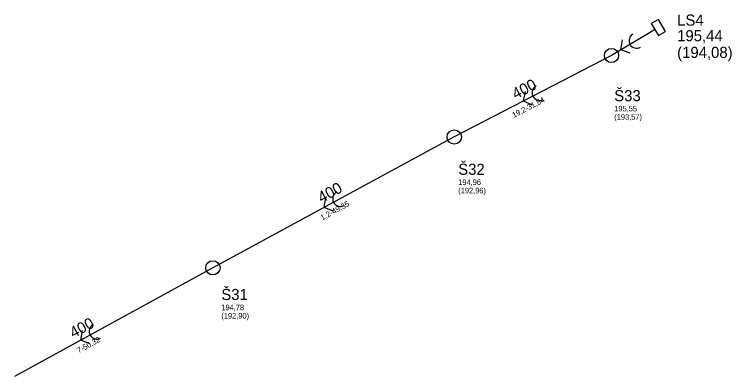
# Model space of a CAD drawing. Extents: x -574467 to -573663, y -1191209 to -1190406.
# Drawn here: x -574467.2 to -574338.3, y -1190987.7 to -1190922.6 of the extents above; entities that cross this region are included whole.
import ezdxf

# ---------------------------------------------------------------- set-up
doc = ezdxf.new("R2010")
doc.units = 0
for name, color, linetype in [('Vrstva 1', 7, 'Continuous'), ('Vrstva 15', 7, 'Continuous'), ('Vrstva 29', 7, 'Continuous'), ('Vrstva 32', 7, 'Continuous'), ('Vrstva 41', 7, 'Continuous'), ('Vrstva 44', 7, 'Continuous'), ('Vrstva 45', 7, 'Continuous'), ('Vrstva 56', 7, 'Continuous'), ('Vrstva 57', 7, 'Continuous')]:
    doc.layers.add(name, color=color, linetype=linetype)

# ---------------------------------------------------------------- blocks, each defined once
blk = doc.blocks.new('100')
at = {"layer": 'Vrstva 1'}
blk.add_circle((0, 0), 1.27, dxfattribs=at)
blk = doc.blocks.new('86')
at = {"layer": 'Vrstva 1'}
blk.add_lwpolyline([(0.79, 1.37), (1.89, 0), (0.79, -1.38)], dxfattribs=at)
blk.add_arc((-1.37, 0), 1.37, 270, 90, dxfattribs=at)

msp = doc.modelspace()

# ---------------------------------------------------------------- linework, layer by layer
at = {"layer": 'Vrstva 15'}
for p, q in [((-574359.849, -1190930.031), (-574388.129, -1190944.665)), ((-574388.129, -1190944.665), (-574431.52, -1190968.171)), ((-574431.52, -1190968.171), (-574467.214, -1190987.714))]:
    msp.add_line(p, q, dxfattribs=at)
msp.add_lwpolyline([(-574352.063, -1190925.38), (-574353.177, -1190926.05), (-574359.849, -1190930.031)], dxfattribs=at)
at = {"layer": 'Vrstva 32'}
msp.add_lwpolyline([(-574351.401, -1190923.542), (-574352.695, -1190924.301), (-574351.431, -1190926.458), (-574350.137, -1190925.699), (-574351.401, -1190923.542)], dxfattribs=at)

# ---------------------------------------------------------------- block references
at = {"layer": 'Vrstva 29'}
for p, xscale, yscale, rotation in [((-574359.849, -1190930.031), 1.0072562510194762, 1.0072562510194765, -151.23333635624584), ((-574388.129, -1190944.665), 1.0106517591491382, 1.010651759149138, -151.83788415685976), ((-574431.52, -1190968.171), 1.0072562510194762, 1.0072562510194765, -151.23333635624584)]:
    msp.add_blockref('100', p, dxfattribs=dict(at, xscale=xscale, yscale=yscale, rotation=rotation))
at = {"layer": 'Vrstva 41'}
for p, xscale, yscale, rotation in [((-574356.513, -1190928.041), 0.9999999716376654, 0.9999999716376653, -150.00000103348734), ((-574373.989, -1190937.348), 1.0138864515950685, 1.0138864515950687, -152.4346848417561), ((-574409.824, -1190956.418), 1.0106517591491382, 1.010651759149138, -151.83788415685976), ((-574453.588, -1190980.254), 1.0072562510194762, 1.0072562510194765, -151.23333635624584)]:
    msp.add_blockref('86', p, dxfattribs=dict(at, xscale=xscale, yscale=yscale, rotation=rotation))

# ---------------------------------------------------------------- texts
at = {"layer": 'Vrstva 32'}
for s, p in [('LS4', (-574348.05, -1190924.669)), ('195,44 ', (-574348.05, -1190927.469)), ('(194,08)', (-574348.05, -1190930.469))]:
    msp.add_text(s, height=2, dxfattribs=at).set_placement(p)
at = {"layer": 'Vrstva 44'}
for rotation, p in [(27.36, (-574377.097, -1190937.947)), (28.45, (-574411.985, -1190956.563)), (28.7, (-574456.58, -1190980.864))]:
    msp.add_text('400', height=2, rotation=rotation, dxfattribs=at).set_placement(p)
at = {"layer": 'Vrstva 45'}
for s, rotation, p in [('19,2-31,84', 27.36, (-574377.411, -1190941.255)), ('1,2-49,35', 28.45, (-574411.84, -1190959.673)), ('7-50,32', 28.7, (-574455.626, -1190983.534))]:
    msp.add_text(s, height=1, rotation=rotation, dxfattribs=at).set_placement(p)
at = {"layer": 'Vrstva 56'}
for s, p in [('195,55 ', (-574359.359, -1190940.071)), ('(193,57)', (-574359.359, -1190941.571)), ('194,96 ', (-574387.409, -1190953.295)), ('(192,96)', (-574387.409, -1190954.795)), ('194,78 ', (-574430, -1190975.781)), ('(192,90)', (-574430, -1190977.281))]:
    msp.add_text(s, height=1, dxfattribs=at).set_placement(p)
at = {"layer": 'Vrstva 57'}
for s, p in [('Š33', (-574359.359, -1190938.241)), ('Š32', (-574387.409, -1190951.465)), ('Š31', (-574430, -1190973.951))]:
    msp.add_text(s, height=2, dxfattribs=at).set_placement(p)

doc.saveas('drawing.dxf')
